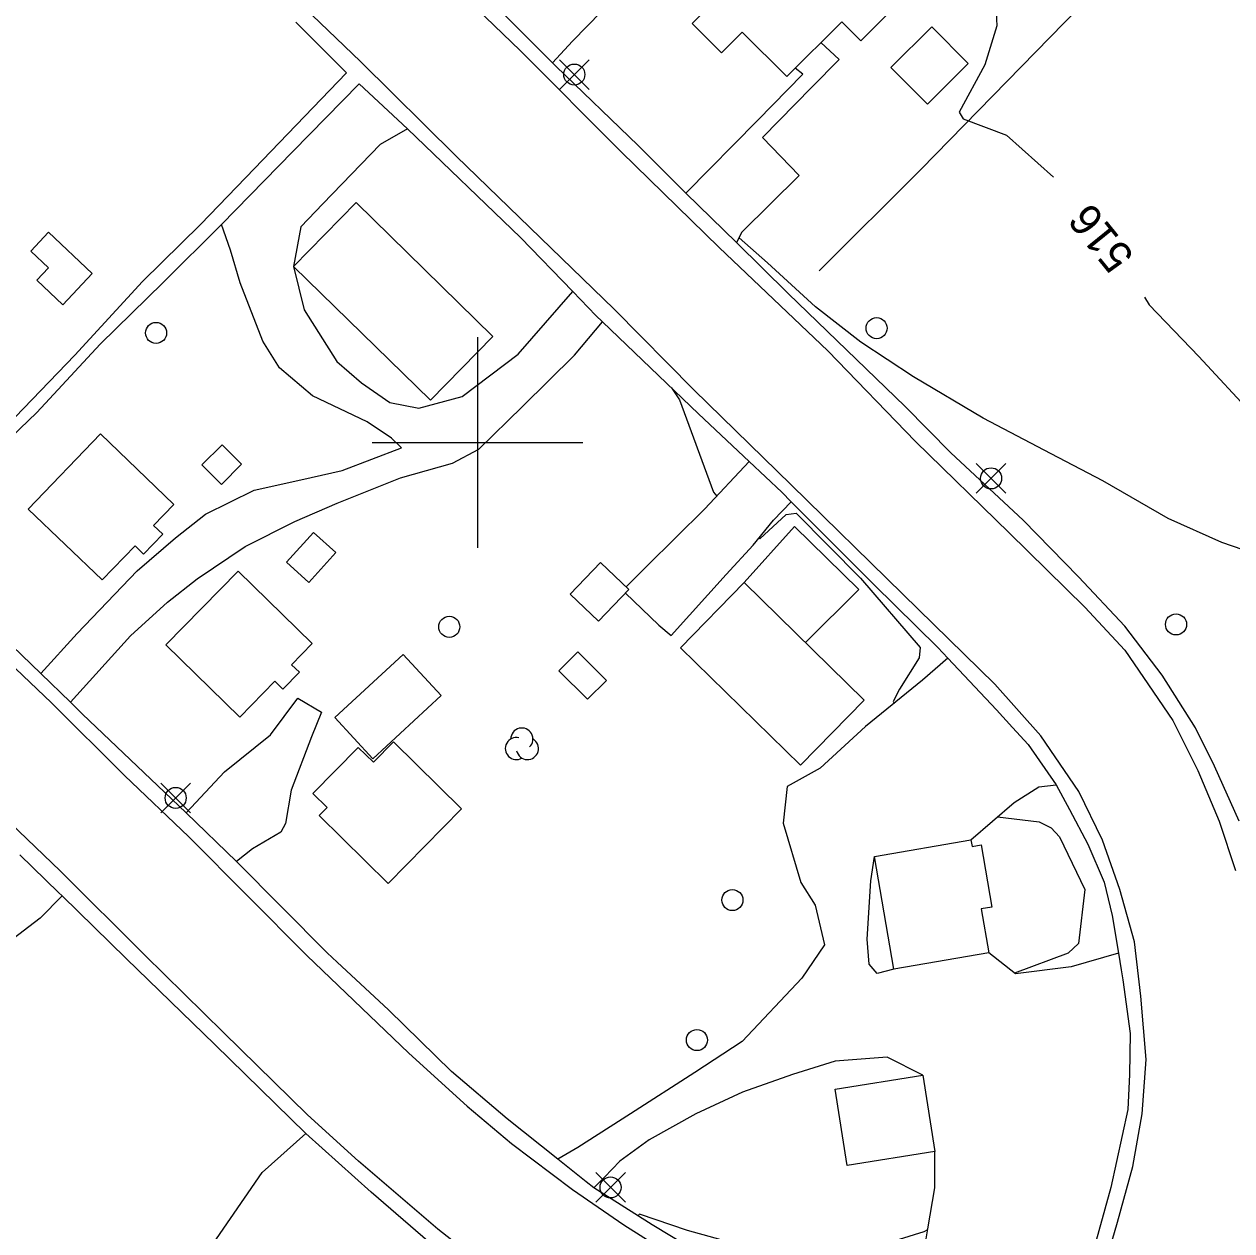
# Model space of a CAD drawing. Extents: x 347312 to 350503, y 6073086 to 6076432.
# Drawn here: x 348656.9 to 348771.6, y 6074525.1 to 6074639.7 of the extents above; entities that cross this region are included whole.
import ezdxf

# ---------------------------------------------------------------- set-up
doc = ezdxf.new("R2010")
doc.units = 0
for name, color, linetype in [('Level 19', 7, 'Continuous'), ('Level 2', 7, 'Continuous'), ('Level 21', 7, 'Continuous'), ('Level 22', 7, 'Continuous'), ('Level 31', 7, 'Continuous'), ('Level 36', 7, 'Continuous'), ('Level 37', 7, 'Continuous'), ('Level 44', 7, 'Continuous'), ('Level 61', 7, 'Continuous')]:
    doc.layers.add(name, color=color, linetype=linetype)

msp = doc.modelspace()

# ---------------------------------------------------------------- linework, layer by layer
at = {"layer": 'Level 19'}
for points in [[(348718.65, 6074646.63), (348717.91, 6074647.36), (348714.52, 6074643.75), (348709, 6074638.1), (348707.11, 6074636.05)], [(348732.6, 6074637.97), (348734.32, 6074636.37), (348731.72, 6074633.73), (348727.04, 6074628.96), (348730.53, 6074625.35), (348725.1, 6074619.95), (348724.58, 6074618.98)], [(348719.78, 6074623.66), (348726.57, 6074630.58), (348730.88, 6074634.96), (348730.16, 6074635.52)], [(348693.34, 6074629.77), (348690.76, 6074628.28), (348685.31, 6074622.64), (348683.2, 6074620.48), (348682.53, 6074616.71), (348683.54, 6074612.6), (348686.63, 6074607.7), (348688.99, 6074605.66), (348691.66, 6074603.8), (348694.43, 6074603.26), (348698.54, 6074604.36), (348703.84, 6074608.37), (348709.03, 6074614.32)], [(348658.53, 6074578.05), (348661.97, 6074581.86), (348667.68, 6074587.8), (348671.31, 6074590.93), (348674.17, 6074593.18), (348678.79, 6074595.47), (348683.21, 6074596.46), (348687.13, 6074597.34), (348692.76, 6074599.49), (348691.83, 6074600.41), (348689.51, 6074601.95), (348684.32, 6074604.41), (348681.2, 6074607.09), (348679.62, 6074609.63), (348677.45, 6074615.16), (348676.55, 6074618.24), (348675.68, 6074620.69)], [(348661.33, 6074575.33), (348667.04, 6074581.65), (348670.55, 6074584.83), (348673.36, 6074587.04), (348677.93, 6074590.12), (348682.63, 6074592.49), (348686.67, 6074594.22), (348692.69, 6074596.63), (348697.6, 6074598.03), (348700.1, 6074599.37), (348704.25, 6074603.4), (348709.19, 6074608.3), (348711.85, 6074611.46)], [(348725.79, 6074598.18), (348721.57, 6074593.71), (348716.05, 6074588.24), (348714.11, 6074586.28)], [(348714.02, 6074585.71), (348717.19, 6074582.65), (348718.38, 6074581.66), (348723.61, 6074587.46), (348726.17, 6074590.26), (348728.09, 6074592.63), (348729.78, 6074594.35)], [(348744.64, 6074579.52), (348742.25, 6074577.42), (348736.83, 6074573.02), (348732.52, 6074569.09), (348729.4, 6074567.34), (348729, 6074563.86), (348730.69, 6074558.23), (348732.05, 6074556.06), (348732.94, 6074552.3), (348730.77, 6074549.15), (348725.13, 6074543.12), (348720.61, 6074540.18), (348714.51, 6074536.24), (348709.51, 6074533.06), (348707.6, 6074531.96)], [(348672.32, 6074564.83), (348675.98, 6074568.74), (348680.33, 6074572.25), (348682.93, 6074575.72), (348685.17, 6074574.4), (348684.24, 6074572.05), (348682.29, 6074567), (348681.76, 6074563.83), (348681.32, 6074563.01), (348678.61, 6074561.4), (348677.1, 6074560.2)], [(348746.84, 6074562.26), (348750.93, 6074565.81), (348753.28, 6074567.31), (348754.92, 6074567.5)], [(348739.52, 6074550), (348737.92, 6074549.58), (348737.18, 6074550.46), (348736.99, 6074552.85), (348737.33, 6074558.38), (348737.69, 6074560.69)], [(348660.57, 6074556.94), (348658.45, 6074554.84), (348648.59, 6074547.3), (348639.7, 6074542.02), (348635.29, 6074539.75), (348633.66, 6074536.38)], [(348760.84, 6074551.52), (348756.37, 6074550.21), (348751.07, 6074549.55), (348748.54, 6074551.55)], [(348742.26, 6074539.92), (348738.89, 6074541.62), (348733.94, 6074541.25), (348729.9, 6074539.99), (348725.15, 6074538.3), (348720.71, 6074536.25), (348716.3, 6074533.79), (348713.5, 6074531.76), (348712.05, 6074530.25), (348711.02, 6074529.23)], [(348746.94, 6074511.31), (348747.31, 6074513.57), (348745.96, 6074515), (348743.18, 6074515.99), (348741.45, 6074516.8), (348741.31, 6074518.78), (348742.15, 6074521.73), (348742.73, 6074525.35), (348743.41, 6074529.22), (348743.42, 6074532.67)]]:
    msp.add_lwpolyline(points, dxfattribs=at)
at = {"layer": 'Level 2'}
for points in [[(348749.05, 6074644.64), (348749.29, 6074639.54), (348748.15, 6074635.85), (348745.71, 6074631.37), (348746.1, 6074630.72), (348750.22, 6074629.18), (348754.69, 6074625.18)], [(348773.71, 6074602.54), (348775.66, 6074599.9), (348776.75, 6074597.49), (348776.15, 6074595.51), (348774.7, 6074593.76), (348774.68, 6074592.67), (348775.12, 6074591.84), (348774.9, 6074590.99), (348774.25, 6074590.17), (348772.7, 6074589.81), (348770.66, 6074590.5), (348765.57, 6074592.77), (348759.36, 6074596.37), (348754.44, 6074598.91), (348747.99, 6074602.32), (348741.38, 6074606.24), (348736.37, 6074609.52), (348732.09, 6074612.88), (348727.52, 6074617.06), (348724.82, 6074619.44)], [(348763.31, 6074613.78), (348763.77, 6074613.06), (348768.47, 6074608.16), (348768.47, 6074608.16), (348773.71, 6074602.54)], [(348718.42, 6074605.17), (348719.18, 6074604.05), (348722.38, 6074595.29), (348722.7, 6074594.91)], [(348726.71, 6074590.93), (348726.81, 6074590.84), (348729.31, 6074593.17), (348730.26, 6074593.28), (348736.34, 6074587.11), (348742.02, 6074580.52), (348741.93, 6074579.54), (348740.04, 6074576.58), (348739.44, 6074575.4), (348739.54, 6074575.22)], [(348749.36, 6074564.45), (348753.32, 6074563.98), (348754.45, 6074563.42), (348755.24, 6074562.56), (348757.65, 6074557.56), (348757.04, 6074552.42), (348756.06, 6074551.52), (348750.98, 6074549.61)], [(348742.71, 6074525.23), (348742.38, 6074525.05), (348738.59, 6074523.87), (348732.84, 6074523.58), (348724.61, 6074523.88), (348719.94, 6074525.17), (348715.36, 6074526.73), (348715.21, 6074526.57)]]:
    msp.add_lwpolyline(points, dxfattribs=at)
at = {"layer": 'Level 21'}
for points in [[(348585.9, 6074647.36), (348597.48, 6074635.74), (348608.59, 6074624.43), (348611.5, 6074621.72), (348620.94, 6074612.88), (348628.61, 6074605.45), (348632.8, 6074601.29), (348638.41, 6074595.71), (348644.63, 6074589.63), (348650.66, 6074583.73), (348659.54, 6074575.29), (348666.46, 6074568.38), (348672.58, 6074562.54), (348683.78, 6074551.29), (348693.48, 6074542.03), (348699.01, 6074536.99), (348703.23, 6074533.43), (348709.02, 6074529.06), (348713.88, 6074525.73), (348720.08, 6074521.78)], [(348692.48, 6074648.36), (348704.03, 6074637.21), (348713.63, 6074627.6), (348722.94, 6074618.52), (348733.25, 6074608.69), (348741.57, 6074600.08), (348750.46, 6074591.41), (348757.65, 6074584.35), (348761.46, 6074580.29), (348763.23, 6074577.69), (348766.02, 6074573.6), (348768.38, 6074568.84), (348770.41, 6074564.04), (348771.96, 6074559.36)], [(348756.88, 6074512.72), (348760.75, 6074525.96), (348762.2, 6074531.26), (348763.09, 6074536.25), (348763.47, 6074541.41), (348762.98, 6074547.43), (348762.37, 6074552.6), (348760.97, 6074557.55), (348759.34, 6074562.24), (348757.09, 6074566.86), (348753.47, 6074572.14), (348749.11, 6074577.04), (348740.38, 6074585.6), (348729.76, 6074595.99), (348720.52, 6074604.98), (348712.97, 6074612.66), (348697.95, 6074627.18), (348688.87, 6074636.16), (348678.14, 6074646.5)], [(348700.94, 6074521.6), (348696.23, 6074525.29), (348688.7, 6074531.75), (348683.85, 6074536.15), (348675.87, 6074543.97), (348668.41, 6074551.33), (348660.4, 6074559.28), (348651.6, 6074567.72), (348644.39, 6074574.69), (348637.6, 6074581.26), (348633.39, 6074585.38), (348630.78, 6074587.95), (348622.53, 6074596.18), (348612.37, 6074606.07), (348611.5, 6074606.94), (348606.78, 6074611.68), (348602.12, 6074616.35), (348597.32, 6074620.95), (348593.47, 6074624.65), (348592.92, 6074625.17), (348582.64, 6074635.66), (348579.1, 6074639.02), (348575.63, 6074642.3)]]:
    msp.add_lwpolyline(points, dxfattribs=at)
at = {"layer": 'Level 22'}
for points in [[(348772.29, 6074564.03), (348769.97, 6074569.27), (348768.17, 6074572.9), (348765.01, 6074577.9), (348761.46, 6074582.56), (348757.05, 6074587.25), (348751.79, 6074592.61), (348744.92, 6074599.02), (348740.6, 6074603.42), (348729.47, 6074614.15), (348724.58, 6074618.98), (348719.78, 6074623.66), (348719.19, 6074624.23), (348715.24, 6074628.19), (348707.43, 6074635.73), (348707.11, 6074636.05), (348701.42, 6074641.75)], [(348682.73, 6074639.9), (348687.55, 6074635.08), (348678, 6074625.15), (348673.68, 6074620.68), (348668.17, 6074615.29), (348661.75, 6074608.3), (348653.61, 6074599.86), (348646.9, 6074593.39), (348645.86, 6074592.42)], [(348650, 6074595.07), (348658.16, 6074602.84), (348664.17, 6074609.34), (348670.13, 6074615.18), (348675.68, 6074620.69), (348682.47, 6074627.61), (348688.76, 6074634.04), (348693.34, 6074629.77), (348704.07, 6074619.45), (348709.03, 6074614.32), (348711.23, 6074612.05), (348711.85, 6074611.46), (348720.97, 6074602.73), (348725.79, 6074598.18), (348728.87, 6074595.27), (348729.78, 6074594.35), (348737.62, 6074586.5), (348743.68, 6074580.54), (348744.64, 6074579.52), (348749.25, 6074574.62), (348750.79, 6074572.94), (348752.28, 6074571.33), (348754.92, 6074567.5), (348756.19, 6074565.15), (348757.94, 6074561.86), (348759.5, 6074558.25), (348760.25, 6074555.09), (348760.84, 6074551.52), (348761.1, 6074549.94), (348761.26, 6074548.98), (348761.95, 6074543.89), (348761.89, 6074539.98), (348761.72, 6074536.66), (348760.13, 6074529.26), (348757.26, 6074518.98)], [(348723.43, 6074521.58), (348716.56, 6074525.71), (348711.02, 6074529.23), (348710.29, 6074529.81), (348707.6, 6074531.96), (348702.81, 6074535.79), (348697.52, 6074540.28), (348691.53, 6074546.14), (348686.66, 6074550.66), (348685.71, 6074551.54), (348677.1, 6074560.2), (348672.32, 6074564.83), (348670.28, 6074566.81), (348662.5, 6074574.21), (348661.33, 6074575.33), (348658.53, 6074578.05), (348654.88, 6074581.59)], [(348695.96, 6074523.58), (348689.88, 6074528.83), (348683.7, 6074534.39), (348675.04, 6074542.85), (348666.63, 6074551), (348660.57, 6074556.94), (348660.22, 6074557.27), (348656.55, 6074560.84)], [(348657.97, 6074498.18), (348663.42, 6074504.43), (348667.9, 6074511.68), (348674.85, 6074523.89), (348679.54, 6074530.7), (348683.7, 6074534.39)]]:
    msp.add_lwpolyline(points, dxfattribs=at)
at = {"layer": 'Level 31'}
for points in [[(348722.26, 6074641.69), (348717.98, 6074645.96), (348723.13, 6074651.13), (348721.27, 6074652.99), (348724.15, 6074655.88), (348725.96, 6074654.07), (348730.7, 6074658.81), (348741.99, 6074647.55), (348737.46, 6074643.01), (348739.36, 6074641.12), (348736.38, 6074638.13), (348734.57, 6074639.94), (348729.37, 6074634.73), (348725.13, 6074638.95), (348723.17, 6074636.98), (348720.36, 6074639.78), (348722.26, 6074641.69)], [(348739.22, 6074635.6), (348743.11, 6074639.47), (348746.59, 6074635.98), (348742.7, 6074632.11), (348739.22, 6074635.6)], [(348688.47, 6074622.77), (348701.45, 6074610.06), (348695.52, 6074604), (348682.53, 6074616.71), (348688.47, 6074622.77)], [(348663.41, 6074616.03), (348660.61, 6074613.08), (348658.16, 6074615.4), (348659.26, 6074616.57), (348657.58, 6074618.16), (348659.27, 6074619.95), (348663.41, 6074616.03)], [(348664.19, 6074600.81), (348671.15, 6074594.12), (348669.23, 6074592.12), (348670.1, 6074591.28), (348668.29, 6074589.4), (348667.47, 6074590.18), (348664.35, 6074586.94), (348657.34, 6074593.68), (348664.19, 6074600.81)], [(348673.82, 6074597.86), (348675.75, 6074599.78), (348677.59, 6074597.93), (348675.67, 6074596.01), (348673.82, 6074597.86)], [(348686.54, 6074589.56), (348683.96, 6074586.71), (348681.85, 6074588.62), (348684.43, 6074591.46), (348686.54, 6074589.56)], [(348683.08, 6074578.18), (348681.52, 6074576.58), (348680.75, 6074577.33), (348677.41, 6074573.92), (348670.41, 6074580.77), (348677.25, 6074587.77), (348684.28, 6074580.9), (348682.32, 6074578.9), (348683.08, 6074578.18)], [(348714.35, 6074586.05), (348711.47, 6074583.02), (348708.78, 6074585.58), (348711.66, 6074588.61), (348714.35, 6074586.05)], [(348730.66, 6074569.36), (348719.27, 6074580.51), (348725.31, 6074586.69), (348736.71, 6074575.54), (348730.66, 6074569.36)], [(348686.43, 6074573.89), (348692.92, 6074579.87), (348696.53, 6074575.96), (348690.04, 6074569.97), (348686.43, 6074573.89)], [(348710.42, 6074575.61), (348707.72, 6074578.33), (348709.53, 6074580.13), (348712.23, 6074577.41), (348710.42, 6074575.61)], [(348692.01, 6074571.57), (348698.46, 6074565.22), (348691.5, 6074558.14), (348684.96, 6074564.57), (348685.71, 6074565.34), (348684.36, 6074566.67), (348688.67, 6074571.05), (348690.11, 6074569.64), (348692.01, 6074571.57)], [(348737.69, 6074560.69), (348746.84, 6074562.26), (348746.94, 6074561.63), (348747.82, 6074561.78), (348748.83, 6074555.89), (348747.82, 6074555.72), (348748.54, 6074551.55), (348739.52, 6074550), (348737.69, 6074560.69)], [(348735.1, 6074531.35), (348733.95, 6074538.6), (348742.26, 6074539.92), (348743.42, 6074532.67), (348735.1, 6074531.35)]]:
    msp.add_lwpolyline(points, dxfattribs=at)
at = {"layer": 'Level 36'}
for p, q in [((348707.77, 6074633.52), (348710.59, 6074636.34)), ((348707.77, 6074636.34), (348710.59, 6074633.52)), ((348747.34, 6074595.18), (348750.16, 6074598)), ((348747.34, 6074598), (348750.16, 6074595.18)), ((348669.92, 6074564.84), (348672.74, 6074567.66)), ((348669.92, 6074567.66), (348672.74, 6074564.84)), ((348711.21, 6074527.86), (348714.03, 6074530.68)), ((348711.21, 6074530.68), (348714.03, 6074527.86))]:
    msp.add_line(p, q, dxfattribs=at)
for centre in [(348709.18, 6074634.93), (348737.88, 6074610.85), (348669.47, 6074610.4), (348748.75, 6074596.59), (348697.31, 6074582.49), (348766.31, 6074582.72), (348671.33, 6074566.25), (348724.19, 6074556.55), (348720.82, 6074543.26), (348712.62, 6074529.27)]:
    msp.add_circle(centre, 1, dxfattribs=at)
at = {"layer": 'Level 37'}
for points in [[(348743.39, 6074688.25), (348758.89, 6074673.09), (348773.89, 6074658.43), (348757.07, 6074641.25), (348742.07, 6074625.91), (348732.43, 6074616.3)], [(348725.31, 6074586.69), (348730.09, 6074592.03), (348736.18, 6074586.03), (348731.12, 6074581)]]:
    msp.add_lwpolyline(points, dxfattribs=at)
at = {"layer": 'Level 44'}
for centre, start, end in [((348704.2, 6074571.84), 314.0633, 179.7519), ((348703.68, 6074570.94), 76.8848, 299.5691), ((348704.73, 6074570.94), 192.2171, 59.6742)]:
    msp.add_arc(centre, 1.05, start, end, dxfattribs=at)
at = {"layer": 'Level 61'}
for p, q in [((348700, 6074610), (348700, 6074590)), ((348690, 6074600), (348710, 6074600))]:
    msp.add_line(p, q, dxfattribs=at)

# ---------------------------------------------------------------- texts
at = {"layer": 'Level 2'}
msp.add_text('516', height=3, rotation=128.9723, dxfattribs=at).set_placement((348762.44, 6074617.71))

doc.saveas('drawing.dxf')
